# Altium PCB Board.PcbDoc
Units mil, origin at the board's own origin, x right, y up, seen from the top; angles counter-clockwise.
Board outline 3917.32 x 3145.67 mil, 2 copper layers (Top Layer, Bottom Layer); 52 components, 39 nets, 493 pads, 14 vias.
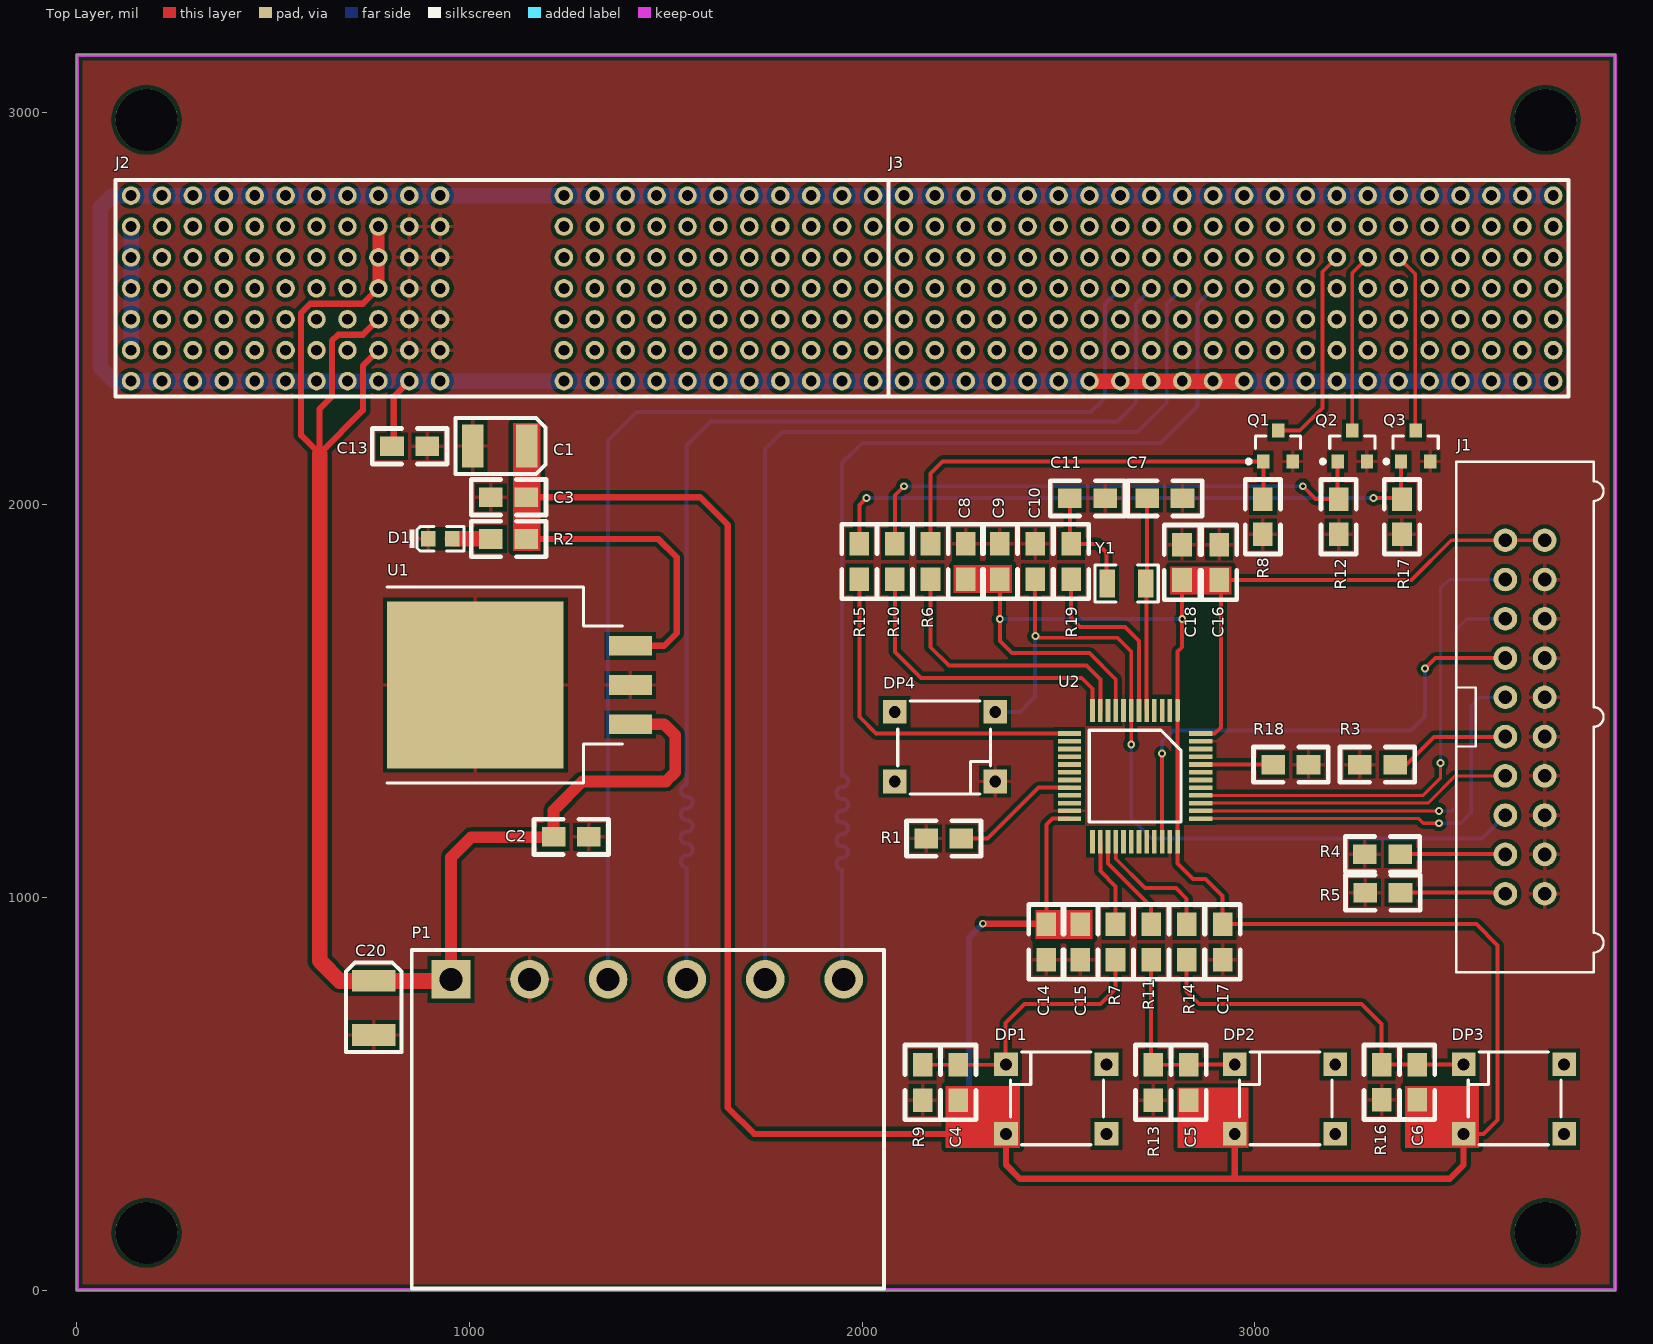
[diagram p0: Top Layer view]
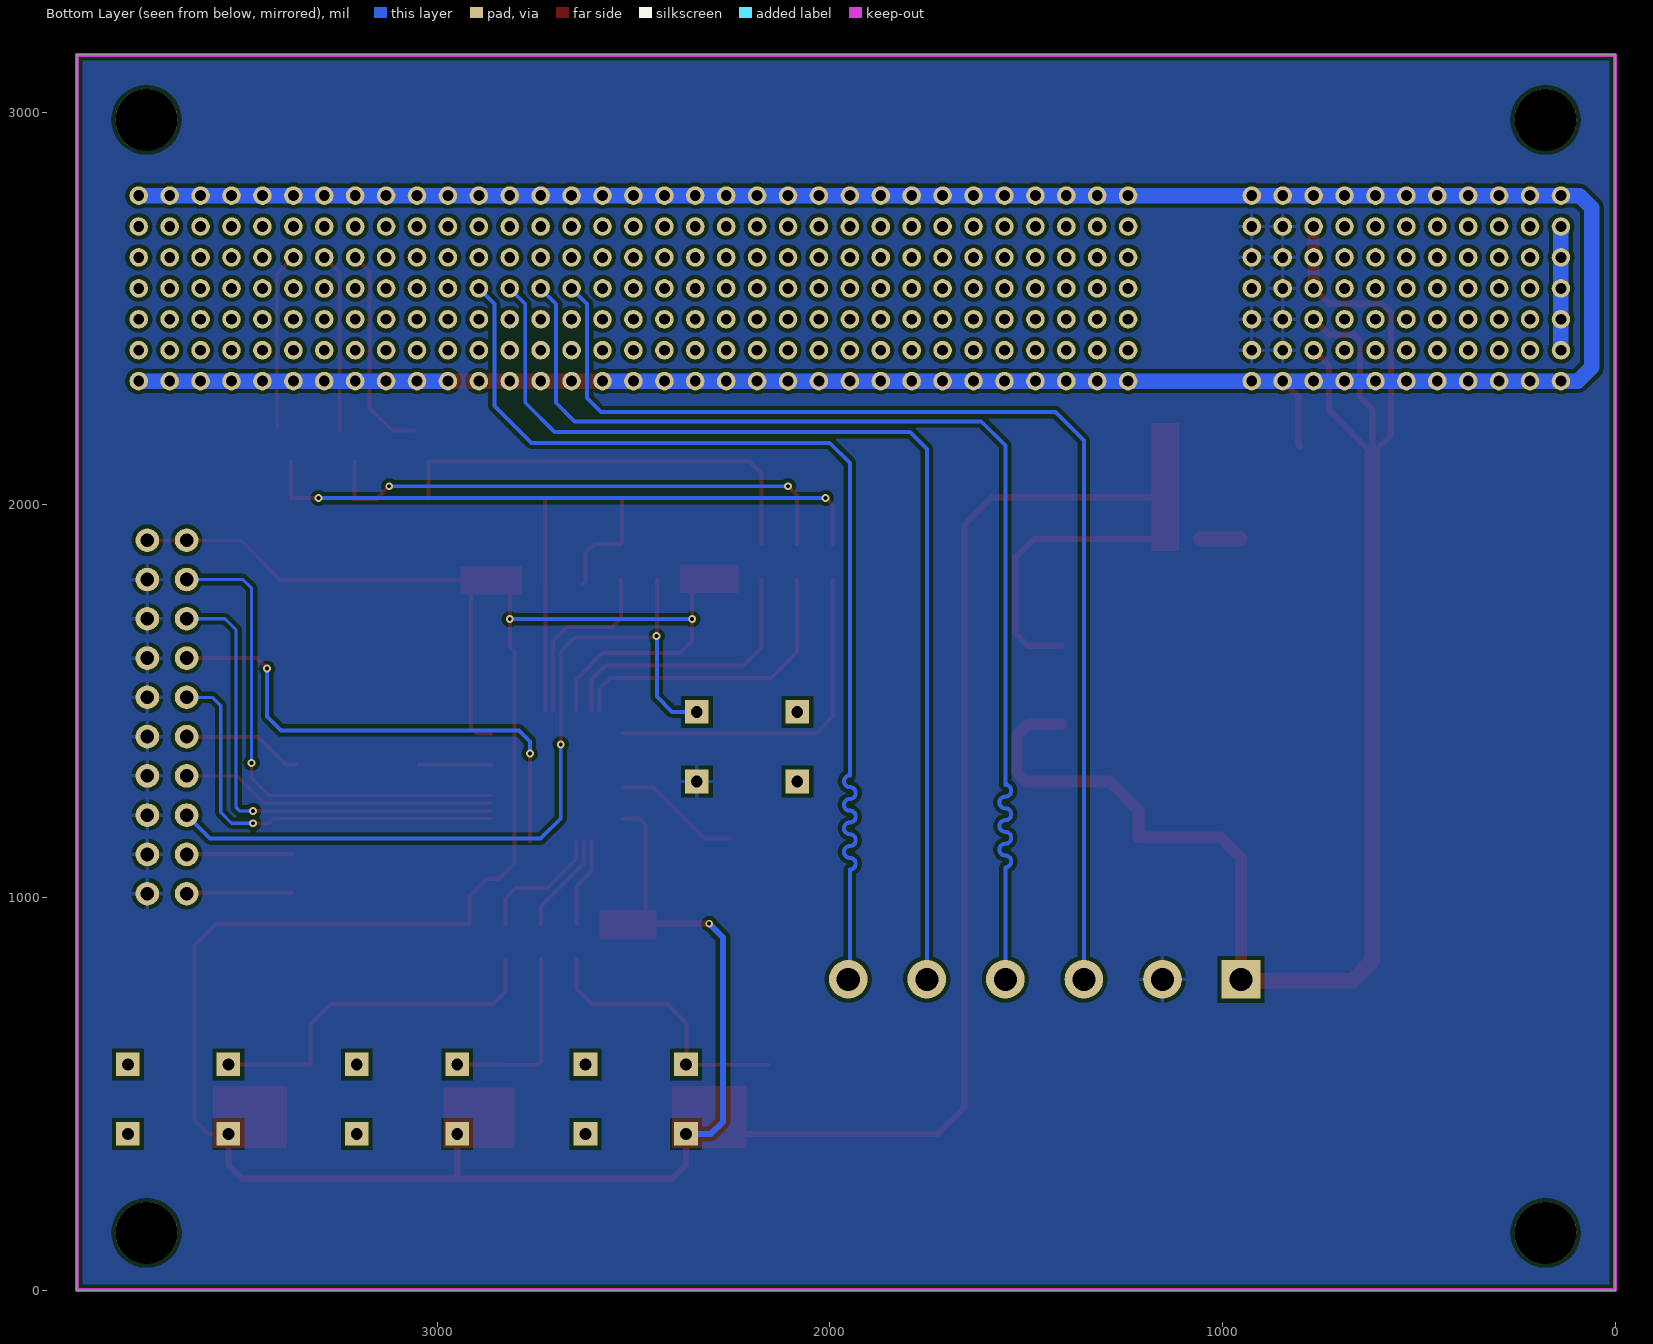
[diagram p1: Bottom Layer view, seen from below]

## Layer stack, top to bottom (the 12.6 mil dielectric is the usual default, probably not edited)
Top Layer: signal copper 1.4
Dielectric: dielectric 12.6, FR-4, Dk 4.8
Bottom Layer: signal copper 1.4

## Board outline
0,3145.67 0,0 3917.32,0 3917.32,3145.67 0,3145.67

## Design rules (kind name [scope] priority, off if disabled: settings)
Clearance Clearance_2 [(InNamedPolygon('Top Layer-No Net 1'))] p1: gap=10
Clearance Clearance_1 [(InComponent('U2'))] p2: gap=7.87
Clearance [All] p3: gap=7.8
ComponentClearance [All] p1: gap=0 collisioncheckmode=3 verticalgap=0 showdistances=FALSE
DiffPairsRouting [All] p1: maxlimit=10 minlimit=10 mostfreqgap=10 maxuncoupledlength=500
PolygonConnect [All] p1: connectstyle=Relief reliefconductorwidth=10 reliefentries=4 polygonreliefangle="90 Angle"
RoutingVias [All] p1: holewidth=10 width=20 viastyle="Through Hole" minholewidth=10 minwidth=20 maxholewidth=28 maxwidth=50
SilkToSilkClearance [All] p1: silktosilkclearance=0
SilkscreenOverComponentPads [All] p1: minsilkscreentomaskgap=0
SolderMaskExpansion [All] p1: expansion=4
Width [All] p1: maxlimit=40 minlimit=5 preferedwidth=10 minimp=50.000000 maximp=50.000000 favimp=50.000000
24 further rules are at their usual default settings.

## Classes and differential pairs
differential pair CAN2: +CAN2_P -CAN2_N
differential pair CAN1: +CAN1_P -CAN1_N

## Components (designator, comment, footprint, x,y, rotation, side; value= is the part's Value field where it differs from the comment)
C1 "106" TC_B_3528 1145.67,2149.61 r180 top
C2 "104" 0805 1303.15,1153.54 r180 top
C3 "104" 0805 1055.12,2019.69 r0 top
C4 "104" 0805 2244.09,484.64 r90 top
C5 "104" 0805 2830.71,484.64 r90 top
C6 "104" 0805 3412.83,484.97 r90 top
C7 "20p" 0805 2814.96,2015.75 r180 top
C8 "104" 0805 2264.33,1899.59 r270 top
C9 "105" 0805 2350.94,1899.59 r270 top
C10 "104" 0805 2440.94,1899.59 r270 top
C11 "20p" 0805 2618.11,2015.75 r180 top
C13 "103" 0805 803.15,2149.61 r0 top
C14 "104" 0805 2468.5,842.52 r90 top
C15 "104" 0805 2555.12,842.52 r90 top
C16 "104" 0805 2909.45,1897.64 r270 top
C17 "106" 0805 2917.32,842.52 r90 top
C18 "104" 0805 2814.96,1897.64 r270 top
C20 "106" TC_B_3528 755.91,787.4 r270 top
D1 "LED" 0603_LED_S1 925.2,1913.39 r0 top
DP1 "SW-PB" PB_6X6 2366.14,574.8 r0 top
DP2 "SW-PB" PB_6X6 2948.82,574.8 r0 top
DP3 "SW-PB" PB_6X6 3531.5,574.8 r0 top
DP4 "SW-PB" PB_6X6 2338.58,1295.28 r180 top
J1 "JTAG-L" JTAG-20P 3692.91,1464.57 r0 top
J2 "CPCI_H2A1541A" CPCI_H2A1541A 137.8,2787.4 r0 top
J3 "CPCI_H2B21541A" CPCI_H2B21541A 2106.3,2787.4 r0 top
P1 "CON-6P" CON-5.08-6P 952.76,791.34 r0 top
Q1 "MMBT4401LT1G" ONSC-SOT-23-3-318-08_V 3059.06,2149.61 r90 top
Q2 "MMBT4401LT1G" ONSC-SOT-23-3-318-08_V 3248.03,2149.61 r90 top
Q3 "MMBT4401LT1G" ONSC-SOT-23-3-318-08_V 3409.45,2149.61 r90 top
R1 "10K" 0805 2251.97,1149.61 r180 top
R2 "1K" 0805 1055.12,1913.39 r0 top
R3 "10K" 0805 3267.72,1338.58 r0 top
R4 "10K" 0805 3369.36,1109.69 r180 top
R5 "10K" 0805 3370.08,1011.81 r180 top
R6 "1K" 0805 2173.23,1811.02 r90 top
R7 "1K" 0805 2645.67,931.08 r270 top
R8 "10K" 0805 3019.68,1925.2 r90 top
R9 "4K7" 0805 2153.54,484.64 r90 top
R10 "1K" 0805 2082.68,1811.02 r90 top
R11 "1K" 0805 2736.22,931.08 r270 top
R12 "10K" 0805 3212.6,1925.2 r90 top
R13 "4K7" 0805 2740.16,484.64 r90 top
R14 "1K" 0805 2826.77,931.08 r270 top
R15 "1K" 0805 1992.13,1811.02 r90 top
R16 "4K7" 0805 3322.28,484.97 r90 top
R17 "10K" 0805 3374.02,1925.2 r90 top
R18 "10K" 0805 3047.24,1338.58 r0 top
R19 "0R" 0805 2531.5,1811.02 r90 top
U1 "MIC29150" TO263 1409.45,1440.94 r90 top
U2 "STM32F103C8T6" LQFP48 2803.15,1476.38 r270 top
Y1 "8MHz" "SMD-3215_2P FC - 135" 2673.23,1799.21 r0 top

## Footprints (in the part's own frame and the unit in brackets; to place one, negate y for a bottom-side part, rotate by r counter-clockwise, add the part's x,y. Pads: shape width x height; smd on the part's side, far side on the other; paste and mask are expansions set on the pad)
0603_LED_S1 [mm]
  rect 0.93x0.98 smd: A(0.77,0) K(-0.77,0)
  silkscreen extent -1.98,-0.79 1.54,0.79, body extent -0.8,-0.4 0.8,0.4, height 0.6
0805 [mil]
  rect 60x50 smd: 1(-0.72,-0.55) 2(89.28,-0.55)
  silkscreen extent -51,-46 139,44
CON-5.08-6P [mm]
  rect 2.5x2.5 hole 1.5: 1(0,0)
  round 2.5 hole 1.5 paste+0: 2(5.08,0) 3(10.16,0) 4(15.24,0) 5(20.32,0) 6(25.4,0)
  silkscreen extent -2.54,-20 28,1.91
CPCI_H2A1541A [mm]
  round 1.2 hole 0.7: A1(0,0) A2(2,0) A3(4,0) A4(6,0) A5(8,0) A6(10,0) A7(12,0) A8(14,0) A9(16,0) A10(18,0) A11(20,0) A15(28,0) A16(30,0) A17(32,0) A18(34,0) A19(36,0) A20(38,0) A21(40,0) A22(42,0) A23(44,0) A24(46,0) A25(48,0) B1(0,-2) B2(2,-2) B3(4,-2) B4(6,-2) B5(8,-2) B6(10,-2) B7(12,-2) B8(14,-2) B9(16,-2) B10(18,-2) B11(20,-2) B15(28,-2) B16(30,-2) B17(32,-2) B18(34,-2) B19(36,-2) B20(38,-2) B21(40,-2) B22(42,-2) B23(44,-2) B24(46,-2) B25(48,-2) C1(0,-4) C2(2,-4) C3(4,-4) C4(6,-4) C5(8,-4) C6(10,-4) C7(12,-4) C8(14,-4) C9(16,-4) C10(18,-4) C11(20,-4) C15(28,-4) C16(30,-4) C17(32,-4) C18(34,-4) C19(36,-4) C20(38,-4) C21(40,-4) C22(42,-4) C23(44,-4) C24(46,-4) C25(48,-4) D1(0,-6) D2(2,-6) D3(4,-6) D4(6,-6) D5(8,-6) D6(10,-6) D7(12,-6) D8(14,-6) D9(16,-6) D10(18,-6) D11(20,-6) D15(28,-6) D16(30,-6) D17(32,-6) D18(34,-6) D19(36,-6) D20(38,-6) D21(40,-6) D22(42,-6) D23(44,-6) D24(46,-6) D25(48,-6) E1(0,-8) E2(2,-8) E3(4,-8) E4(6,-8) E5(8,-8) E6(10,-8) E7(12,-8) E8(14,-8) E9(16,-8) E10(18,-8) E11(20,-8) E15(28,-8) E16(30,-8) E17(32,-8) E18(34,-8) E19(36,-8) E20(38,-8) E21(40,-8) E22(42,-8) E23(44,-8) E24(46,-8) E25(48,-8) F1(0,-10) F2(2,-10) F3(4,-10) F4(6,-10) F5(8,-10) F6(10,-10) F7(12,-10) F8(14,-10) F9(16,-10) F10(18,-10) F11(20,-10) F15(28,-10) F16(30,-10) F17(32,-10) F18(34,-10) F19(36,-10) F20(38,-10) F21(40,-10) F22(42,-10) F23(44,-10) F24(46,-10) F25(48,-10) G1(0,-12) G2(2,-12) G3(4,-12) G4(6,-12) G5(8,-12) G6(10,-12) G7(12,-12) G8(14,-12) G9(16,-12) G10(18,-12) G11(20,-12) G15(28,-12) G16(30,-12) G17(32,-12) G18(34,-12) G19(36,-12) G20(38,-12) G21(40,-12) G22(42,-12) G23(44,-12) G24(46,-12) G25(48,-12)
  silkscreen extent -1,-13 49,1
CPCI_H2B21541A [mm]
  round 1.2 hole 0.7: A1(0,0) A2(2,0) A3(4,0) A4(6,0) A5(8,0) A6(10,0) A7(12,0) A8(14,0) A9(16,0) A10(18,0) A11(20,0) A12(22,0) A13(24,0) A14(26,0) A15(28,0) A16(30,0) A17(32,0) A18(34,0) A19(36,0) A20(38,0) A21(40,0) A22(42,0) B1(0,-2) B2(2,-2) B3(4,-2) B4(6,-2) B5(8,-2) B6(10,-2) B7(12,-2) B8(14,-2) B9(16,-2) B10(18,-2) B11(20,-2) B12(22,-2) B13(24,-2) B14(26,-2) B15(28,-2) B16(30,-2) B17(32,-2) B18(34,-2) B19(36,-2) B20(38,-2) B21(40,-2) B22(42,-2) C1(0,-4) C2(2,-4) C3(4,-4) C4(6,-4) C5(8,-4) C6(10,-4) C7(12,-4) C8(14,-4) C9(16,-4) C10(18,-4) C11(20,-4) C12(22,-4) C13(24,-4) C14(26,-4) C15(28,-4) C16(30,-4) C17(32,-4) C18(34,-4) C19(36,-4) C20(38,-4) C21(40,-4) C22(42,-4) D1(0,-6) D2(2,-6) D3(4,-6) D4(6,-6) D5(8,-6) D6(10,-6) D7(12,-6) D8(14,-6) D9(16,-6) D10(18,-6) D11(20,-6) D12(22,-6) D13(24,-6) D14(26,-6) D15(28,-6) D16(30,-6) D17(32,-6) D18(34,-6) D19(36,-6) D20(38,-6) D21(40,-6) D22(42,-6) E1(0,-8) E2(2,-8) E3(4,-8) E4(6,-8) E5(8,-8) E6(10,-8) E7(12,-8) E8(14,-8) E9(16,-8) E10(18,-8) E11(20,-8) E12(22,-8) E13(24,-8) E14(26,-8) E15(28,-8) E16(30,-8) E17(32,-8) E18(34,-8) E19(36,-8) E20(38,-8) E21(40,-8) E22(42,-8) F1(0,-10) F2(2,-10) F3(4,-10) F4(6,-10) F5(8,-10) F6(10,-10) F7(12,-10) F8(14,-10) F9(16,-10) F10(18,-10) F11(20,-10) F12(22,-10) F13(24,-10) F14(26,-10) F15(28,-10) F16(30,-10) F17(32,-10) F18(34,-10) F19(36,-10) F20(38,-10) F21(40,-10) F22(42,-10) G1(0,-12) G2(2,-12) G3(4,-12) G4(6,-12) G5(8,-12) G6(10,-12) G7(12,-12) G8(14,-12) G9(16,-12) G10(18,-12) G11(20,-12) G12(22,-12) G13(24,-12) G14(26,-12) G15(28,-12) G16(30,-12) G17(32,-12) G18(34,-12) G19(36,-12) G20(38,-12) G21(40,-12) G22(42,-12)
  silkscreen extent -1,-13 43,1
JTAG-20P [mil]
  round 60 hole 35: 1(-55,445) 2(45,445) 3(-55,345) 4(45,345) 5(-55,245) 6(45,245) 7(-55,145) 8(45,145) 9(-55,45) 10(45,45) 11(-55,-55) 12(45,-55) 13(-55,-155) 14(45,-155) 15(-55,-255) 16(45,-255) 17(-55,-355) 18(45,-355) 19(-55,-455) 20(45,-455)
  silkscreen extent -180,-655 195,645
LQFP48 [mm]
  oval 1.5x0.3 smd: 1(0,0)
  rect 1.5x0.3 smd: 2(0,-0.5) 3(0,-1) 4(0,-1.5) 5(0,-2) 6(0,-2.5) 7(0,-3) 8(0,-3.5) 9(0,-4) 10(0,-4.5) 11(0,-5) 12(0,-5.5) 25(8.5,-5.5) 26(8.5,-5) 27(8.5,-4.5) 28(8.5,-4) 29(8.5,-3.5) 30(8.5,-3) 31(8.5,-2.5) 32(8.5,-2) 33(8.5,-1.5) 34(8.5,-1) 35(8.5,-0.5) 36(8.5,0)
  rect 0.3x1.5 smd: 13(1.5,-7) 14(2,-7) 15(2.5,-7) 16(3,-7) 17(3.5,-7) 18(4,-7) 19(4.5,-7) 20(5,-7) 21(5.5,-7) 22(6,-7) 23(6.5,-7) 24(7,-7) 37(7,1.5) 38(6.5,1.5) 39(6,1.5) 40(5.5,1.5) 41(5,1.5) 42(4.5,1.5) 43(4,1.5) 44(3.5,1.5) 45(3,1.5) 46(2.5,1.5) 47(2,1.5) 48(1.5,1.5)
  silkscreen extent 1.28,-5.71 7.21,0.22
ONSC-SOT-23-3-318-08_V [mm] "SOT23, 3-Leads, Body 2.92x1.3mm, Pitch 0.95mm"
  rect 0.9x0.8 smd: 1(-1,0.95) 2(-1,-0.95) 3(1,0)
  silkscreen extent -1.12,-1.46 0.65,2.02, body extent -0.65,-1.46 0.65,1.46, height 1.11
PB_6X6 [mil]
  rect 60x60 hole 30: 1(0,0) 2(0,-177.17) 3(255.91,0) 4(255.91,-177.17)
  silkscreen extent 12,-205 248,31
"SMD-3215_2P FC - 135" [mm]
  rect 1x1.8 smd: 1(-1.25,0) 2(1.25,0)
  silkscreen extent -2.05,-1.2 2.05,1.2
TC_B_3528 [mm]
  rect 1.4x2.8 smd: 1(0,0) 2(3.5,0)
  silkscreen extent -1.2,-1.8 4.6,1.8
TO263 [mil]
  rect 50x110 smd: 1(0,0) 2(100,0) 3(200,0)
  rect 425x450 smd: 4(100,394.69)
  silkscreen extent -150,20 350,620

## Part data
C1 C20: library part "CAP POL1", "Capacitor"
C2 C3 C4 C5 C6 C7 C8 C9 C10 C11 C13 C14 C15 C16 C17 C18: library part CAP
DP1 DP2 DP3 DP4: "Key"
J1: "Connector"
Q1 Q2 Q3: "Switching Transistor, NPN Silicon, 3-Pin SOT-23, Pb-Free, Tape and Reel"
R1 R2 R3 R4 R5 R6 R7 R8 R9 R10 R11 R12 R13 R14 R15 R16 R17 R18 R19: library part RES1
U2: library part STM32F103C6T6, "ST ARM-based 32-bit MCU with 32 KB Flash, USB, CAN, 7 timers, 2 ADCs, 9 com. interfaces"
Y1: library part "XTAL-3215_2P 32.768KHz", "ÌùÆ¬¾"

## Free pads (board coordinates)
  round 157.48 hole 157.48: 0(177.17,145.67) 1(3740.16,145.67) 2(3740.16,2980.31) 3(177.17,2980.31)

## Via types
v1: diameter 20, hole 10, Top Layer to Bottom Layer, tented both sides, 14 vias

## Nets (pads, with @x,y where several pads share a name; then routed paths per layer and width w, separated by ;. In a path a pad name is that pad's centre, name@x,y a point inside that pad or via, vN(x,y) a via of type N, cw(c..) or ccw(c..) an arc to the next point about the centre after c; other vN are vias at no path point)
3V3: C1.1 C3.2 C4.1 C5.1 C6.1 C8.2 C9.2 C14.2 C15.2 C16.2 C17.2 C18.2 DP1.2 DP2.2 DP3.2 J1.1 J1.2 R2.2 U1.3 U2.1 U2.9 U2.24 U2.36 U2.48 | length 10644.2
  Top Layer w10: C3.2 C3.2@1160.7,2035.43 ; C9.2 v1(2350.39,1708.66) 2350.39,1653.54 2381.89,1622.05 2578.74,1622.05 2645.67,1555.12 U2.9 ; C14.2 2469.05,1185.59 2484.25,1200.79 U2.24 ; C18.2 2814.41,1637.24 2803.15,1625.98 U2.1 U2.36 2803.15,1086.61 2842.52,1047.24 2874.02,1047.24 2917.87,1003.39 C17.2 3564.26,931.8 3618.11,877.95 3618.11,433.07 3582.68,397.64 DP3.2 ; U2.48 2897.64,1417.32 2913.39,1433.07 2913.39,1803.87 C16.2 3398.91,1808.36 3500.12,1909.57 J1.1 J1.2
  Top Layer w15.75: R2.2 1480.87,1912.83 1527.56,1866.14 1527.56,1673.23 1495.28,1640.94 U1.3 ; C3.2 1587.17,2019.13 1657.48,1948.82 1657.48,464.57 1724.41,397.64 DP1.2 2366.14,318.9 2401.57,283.46 3496.06,283.46 3531.5,318.9 DP3.2 ; v1(2307.09,933.07) 2467.79,933.07 C14.2 ; 2948.82,283.46 DP2.2
  Bottom Layer w10: v1(2350.39,1708.66) v1(2814.96,1708.66)
  Bottom Layer w15.75: v1(2307.09,933.07) 2271.65,897.64 2271.65,429.13 2303.15,397.64 DP1.2
28V: J2.B1 J2.C1 J2.D1 J2.E1 J2.F1 | length 315
  Bottom Layer w39.37: J2.F1 J2.D1 J2.C1 J2.B1
CAN1_N: J3.D9 P1.4 | length 2976.3
  Bottom Layer w10: P1.4 1552.76,1076.69 cw(c1552.76,1091.69) 1552.76,1106.69 ccw(c1552.76,1121.69) 1552.76,1136.69 cw(c1552.76,1151.69) 1552.76,1166.69 ccw(c1552.76,1181.69) 1552.76,1196.69 ; 1552.76,1196.85 cw(c1552.76,1211.85) 1552.76,1226.85 ccw(c1552.76,1241.85) 1552.76,1256.85 cw(c1552.76,1271.85) 1552.76,1286.85 1552.76,2151.18 1614.17,2212.6 2649.61,2212.6 2696.85,2259.84 2696.85,2511.81 J3.D9
CAN1_P: J3.D8 P1.3 | length 2978.3
  Bottom Layer w10: P1.3 1352.76,2163.78 1425.2,2236.22 2582.68,2236.22 2618.11,2271.65 2618.11,2511.81 J3.D8
CAN2_N: J3.D11 P1.6 | length 2733.3
  Bottom Layer w10: P1.6@1948.82,791.34 1948.82,1070.87 cw(c1948.82,1085.87) 1948.82,1100.87 ccw(c1948.82,1115.87) 1948.82,1130.87 cw(c1948.82,1145.87) 1948.82,1160.87 ccw(c1948.82,1175.87) 1948.82,1190.87 cw(c1948.82,1205.87) 1948.82,1220.87 ccw(c1948.82,1235.87) 1948.82,1250.87 cw(c1948.82,1265.87) 1948.82,1280.87 ccw(c1948.82,1295.87) 1948.82,1310.87 1948.82,2106.3 2000,2157.48 2759.84,2157.48 2854.33,2251.97 2854.33,2511.81 J3.D11
CAN2_P: J3.D10 P1.5 | length 2738.1
  Bottom Layer w10: P1.5@1752.76,783.46 1752.76,2142.52 1795.28,2185.04 2700.79,2185.04 2775.59,2259.84 2775.59,2511.81 J3.D10
GND: C1.2 C2.1 C3.1 C7.1 C8.1 C9.1 C10.1 C11.1 C13.2 C14.1 C15.1 C16.1 C17.1 C18.1 C20.2 D1.K DP4.1 J1.4 J1.6 J1.8 J1.10 J1.12 J1.14 J1.16 J1.18 J1.20 J2.B10 J2.B11 J2.C10 J2.C11 J2.D10 J2.E10 J2.E11 J2.F10 J2.F11 P1.2 Q1.2 Q2.2 Q3.2 R1.2 R3.1 R4.2 R5.2 R8.1 R9.1 R12.1 R13.1 R16.1 R17.1 R18.2 U1.2 U1.4 U2.8 U2.23 U2.35 U2.47
KEY_OFF: R11.1 U2.27 | length 255.4
  Top Layer w10: U2.27 2625.98,1086.61 2735.67,976.93 R11.1
KEY_ON: R7.1 U2.26 | length 226
  Top Layer w10: U2.26 2606.3,1066.93 2645.12,1028.11 R7.1
KEY_RESET: R14.1 U2.28 | length 330.8
  Top Layer w10: U2.28 2645.67,1098.42 2720.47,1023.62 2799.21,1023.62 2826.22,996.61 R14.1
NetC4_2: C4.2 DP1.1 R7.2 R9.2 | length 708
  Top Layer w10: R9.2 C4.2 2365.26,573.92 2365.26,680.22 2413.39,728.35 2606.3,728.35 2645.12,767.17 R7.2
NetC5_2: C5.2 DP2.1 R11.2 R13.2 | length 477.2
  Top Layer w10: R11.2 2735.67,578.96 R13.2 C5.2 ; C5.2@2832.14,574.8 DP2.1
NetC6_2: C6.2 DP3.1 R14.2 R16.2 | length 924.3
  Top Layer w10: R14.2 2826.22,760.39 2858.27,728.35 3271.65,728.35 3322.83,677.17 R16.2 C6.2 3530.94,574.25 DP3.1
NetC11_2: C11.2 R19.2 Y1.1 | length 293.2
  Top Layer w10: R19.2@2528.83,1903.52 C11.2 ; R19.2 2599.69,1900.31 2622.05,1877.95 2622.05,1805.12 Y1.1@2627.95,1799.21
NetD1_A: D1.A R2.1 | length 98.3
  Top Layer w39.37: D1.A R2.1@1053.85,1913.39
NetJ1_11: J1.11 R3.2 | length 309.4
  Top Layer w10: R3.2@3357,1338.58 3385.83,1338.58 3456.14,1408.9 J1.11@3637.25,1408.9
NetJ1_17: J1.17 R4.1 | length 267.2
  Top Layer w10: R4.1 J1.17@3637.24,1110.24
NetJ1_19: J1.19 R5.1 | length 264.3
  Top Layer w10: R5.1 J1.19@3635.12,1012.36
NetQ1_1: Q1.1 R6.2 R8.2 | length 1134
  Top Layer w10: R6.2 2173.78,2079.29 2204.72,2110.24 Q1.1 R8.2@3021.65,2015.9
NetQ2_1: Q2.1 R10.2 R12.2 | length 1370.2
  Top Layer w10: R10.2 2083.23,2024.17 v1(2106.3,2047.24) ; v1(3122.05,2047.24) 3154.81,2014.48 R12.2 ; R12.2@3210.63,2017 Q2.1
  Bottom Layer w10: v1(2106.3,2047.24) v1(3122.05,2047.24)
NetQ3_1: Q3.1 R15.2 R17.2 | length 1578.8
  Top Layer w10: R15.2 1992.68,1999.11 v1(2010.56,2017) ; v1(3301.9,2017) 3372.05,2017 Q3.1
  Bottom Layer w10: v1(2010.56,2017) v1(3301.9,2017)
NetR1_1: R1.1 U2.20 | length 328.5
  Top Layer w10: R1.1 2319.45,1150.16 2448.82,1279.53 U2.20
NetR18_1: R18.1 U2.44 | length 183.8
  Top Layer w10: U2.44 R18.1@3045.97,1338.58
NRST: C10.2 DP4.2 J1.15 U2.7 | length 2101.7
  Top Layer w10: C10.2 2440.39,1665.91 v1(2440.94,1665.35) 2444.88,1661.42 2649.61,1661.42 2685.04,1625.98 U2.7 v1(2685.04,1389.76)
  Bottom Layer w10: DP4.2 2401.57,1472.44 2440.39,1511.26 v1@2440.39,1665.35 ; v1(2685.04,1389.76) 2685.04,1200.79 2736.22,1149.61 3577.95,1149.61 J1.15
NTRST: J1.3 U2.40 | length 1287.1
  Top Layer w8: U2.40 3429.13,1259.84 3472.44,1303.15 v1(3472.44,1342.52)
  Bottom Layer w8: v1(3472.44,1342.52) 3472.44,1787.4 3494.61,1809.57 J1.3
OC1_ON: J3.C15 Q1.3 | length 535.2
  Top Layer w10: Q1.3 3114.17,2188.98 3172.17,2246.97 3172.17,2593.43 J3.C15
OC2_OFF: J3.C16 Q2.3 | length 457.3
  Top Layer w10: Q2.3 3248.03,2590.55 J3.C16
OC3_RESET: J3.C17 Q3.3 | length 449.5
  Top Layer w10: J3.C17 3408.39,2587.68 Q3.3@3408.39,2197.91
OSC_IN: C7.2 U2.5 Y1.2 | length 538.8
  Top Layer w10: Y1.2 2723.5,1798.15 U2.5@2723.5,1477.28 ; Y1.2@2725.68,1799.91 C7.2
OSC_OUT: R19.1 U2.6 | length 472.3
  Top Layer w10: R19.1 2532.05,1712.05 2555.12,1688.98 2669.29,1688.98 2704.72,1653.54 U2.6
PGND: C13.1 J2.A1 J2.A2 J2.A3 J2.A4 J2.A5 J2.A6 J2.A7 J2.A8 J2.A9 J2.A10 J2.A11 J2.A15 J2.A16 J2.A17 J2.A18 J2.A19 J2.A20 J2.A21 J2.A22 J2.A23 J2.A24 J2.A25 J2.G1 J2.G2 J2.G3 J2.G4 J2.G5 J2.G6 J2.G7 J2.G8 J2.G9 J2.G10 J2.G11 J2.G15 J2.G16 J2.G17 J2.G18 J2.G19 J2.G20 J2.G21 J2.G22 J2.G23 J2.G24 J2.G25 J3.A1 J3.A2 J3.A3 J3.A4 J3.A5 J3.A6 J3.A7 J3.A8 J3.A9 J3.A10 J3.A11 J3.A12 J3.A13 J3.A14 J3.A15 J3.A16 J3.A17 J3.A18 J3.A19 J3.A20 J3.A21 J3.A22 J3.G1 J3.G2 J3.G3 J3.G4 J3.G5 J3.G6 J3.G7 J3.G8 J3.G9 J3.G10 J3.G11 J3.G12 J3.G13 J3.G14 J3.G15 J3.G16 J3.G17 J3.G18 J3.G19 J3.G20 J3.G21 J3.G22 | length 8022.9
  Top Layer w15.75: C13.1 807.09,2153.71 807.09,2275.59 J2.G10 J2.G10@846.46,2311.02
  Top Layer w39.37: J3.G7 J3.G8 J3.G9 J3.G10 J3.G11 J3.G12
  Bottom Layer w39.37: J3.G7 J3.G6 J3.G5 J3.G4 J3.G3 J3.G2 J3.G1 J2.G25 J2.G24 J2.G23 J2.G22 J2.G21 J2.G20 J2.G19 J2.G18 J2.G17 J2.G16 J2.G15 J2.G11 J2.G10 J2.G9 J2.G7 J2.G6 J2.G5 J2.G4 J2.G3 J2.G2 J2.G1 94.49,2314.96 59.06,2350.39 59.06,2755.91 90.55,2787.4 J2.A1 J2.A2 J2.A3 J2.A4 J2.A5 J2.A6 J2.A7 J2.A8 J2.A9 J2.A10 J2.A11 J2.A15 J2.A16 J2.A17 J2.A18 J2.A19 J2.A20 J2.A21 J2.A22 J2.A23 J2.A24 J2.A25 J3.A1 J3.A2 J3.A3 J3.A4 J3.A5 J3.A6 J3.A7 J3.A8 J3.A9 J3.A10 J3.A11 J3.A12 J3.A13 J3.A14 J3.A15 J3.A16 J3.A17 J3.A18 J3.A19 J3.A20 J3.A21 J3.A22 ; J3.G12 J3.G13 J3.G14 J3.G15 J3.G16 J3.G17 J3.G18 J3.G19 J3.G20 J3.G21 J3.G22
TCK: J1.9 U2.37 | length 1072.5
  Top Layer w8: U2.37 3417.32,1200.79 3429.13,1188.98 v1(3468.5,1188.98)
  Bottom Layer w8: v1(3468.5,1188.98) 3523.62,1188.98 3551.18,1216.54 3551.18,1488.19 3572.56,1509.57 J1.9
TDI: J1.5 U2.38 | length 1243.5
  Top Layer w8: U2.38 v1(3468.5,1220.47)
  Bottom Layer w8: v1(3468.5,1220.47) 3503.94,1220.47 3511.81,1228.35 3511.81,1681.1 3540.28,1709.57 J1.5
TDO: J1.13 U2.39 | length 804.5
  Top Layer w8: U2.39 3440.95,1240.16 3510.35,1309.57 J1.13
TIM2_2: R6.1 U2.11 | length 718.3
  Top Layer w10: R6.1 2173.78,1637.24 2220.47,1590.55 2570.87,1590.55 2606.3,1555.12 U2.11
TIM2_3: R10.1 U2.12 | length 782.3
  Top Layer w10: R10.1 2083.23,1625.43 2149.61,1559.06 2559.06,1559.06 2586.61,1531.5 U2.12
TIM2_4: R15.1 U2.13 | length 902.8
  Top Layer w10: R15.1 1992.68,1460.08 2035.43,1417.32 U2.13
TMS: J1.7 U2.34 | length 1289.3
  Top Layer w10: U2.34 v1(2763.78,1366.14) ; v1(3433.07,1582.68) 3459.96,1609.57 J1.7
  Bottom Layer w10: v1(2763.78,1366.14) 2763.78,1397.64 2791.34,1425.2 3397.64,1425.2 3433.07,1460.63 v1(3433.07,1582.68)
VIN_12V: C2.2 C20.1 J2.B9 J2.C9 J2.D9 J2.E9 J2.F9 P1.1 U1.1 | length 4392.6
  Top Layer w15.74: 618.11,2129.92 728.35,2240.16 728.35,2354.33 J2.F9
  Top Layer w15.75: J2.E9 728.42,2433.14 665.43,2433.14 649.53,2417.25 649.53,2275.66 618.11,2244.24 618.11,2129.92 570.87,2177.17 570.87,2488.64 594.11,2511.89 728.27,2511.89 767.57,2551.18 J2.D9
  Top Layer w30: J2.D9 J2.C9 J2.B9 ; P1.1 952.76,1102.36 1003.94,1153.54 C2.2@1206.54,1153.54 ; C2.2 1213.87,1221.74 1287.4,1295.28 1500,1295.28 1523.62,1318.9 1523.62,1413.39 1496.06,1440.94 U1.1
  Top Layer w40: 618.11,2129.92 618.11,838.58 669.29,787.4 C20.1 P1.1@948.82,787.4
pads on no net: DP1.3 DP1.4 DP2.3 DP2.4 DP3.3 DP3.4 DP4.3 DP4.4 J2.B2 J2.B3 J2.B4 J2.B5 J2.B6 J2.B7 J2.B8 J2.B15 J2.B16 J2.B17 J2.B18 J2.B19 J2.B20 J2.B21 J2.B22 J2.B23 J2.B24 J2.B25 J2.C2 J2.C3 J2.C4 J2.C5 J2.C6 J2.C7 J2.C8 J2.C15 J2.C16 J2.C17 J2.C18 J2.C19 J2.C20 J2.C21 J2.C22 J2.C23 J2.C24 J2.C25 J2.D2 J2.D3 J2.D4 J2.D5 J2.D6 J2.D7 J2.D8 J2.D11 J2.D15 J2.D16 J2.D17 J2.D18 J2.D19 J2.D20 J2.D21 J2.D22 J2.D23 J2.D24 J2.D25 J2.E2 J2.E3 J2.E4 J2.E5 J2.E6 J2.E7 J2.E8 J2.E15 J2.E16 J2.E17 J2.E18 J2.E19 J2.E20 J2.E21 J2.E22 J2.E23 J2.E24 J2.E25 J2.F2 J2.F3 J2.F4 J2.F5 J2.F6 J2.F7 J2.F8 J2.F15 J2.F16 J2.F17 J2.F18 J2.F19 J2.F20 J2.F21 J2.F22 J2.F23 J2.F24 J2.F25 J3.B1 J3.B2 J3.B3 J3.B4 J3.B5 J3.B6 J3.B7 J3.B8 J3.B9 J3.B10 J3.B11 J3.B12 J3.B13 J3.B14 J3.B15 J3.B16 J3.B17 J3.B18 J3.B19 J3.B20 J3.B21 J3.B22 J3.C1 J3.C2 J3.C3 J3.C4 J3.C5 J3.C6 J3.C7 J3.C8 J3.C9 J3.C10 J3.C11 J3.C12 J3.C13 J3.C14 J3.C18 J3.C19 J3.C20 J3.C21 J3.C22 J3.D1 J3.D2 J3.D3 J3.D4 J3.D5 J3.D6 J3.D7 J3.D12 J3.D13 J3.D14 J3.D15 J3.D16 J3.D17 J3.D18 J3.D19 J3.D20 J3.D21 J3.D22 J3.E1 J3.E2 J3.E3 J3.E4 J3.E5 J3.E6 J3.E7 J3.E8 J3.E9 J3.E10 J3.E11 J3.E12 J3.E13 J3.E14 J3.E15 J3.E16 J3.E17 J3.E18 J3.E19 J3.E20 J3.E21 J3.E22 J3.F1 J3.F2 J3.F3 J3.F4 J3.F5 J3.F6 J3.F7 J3.F8 J3.F9 J3.F10 J3.F11 J3.F12 J3.F13 J3.F14 J3.F15 J3.F16 J3.F17 J3.F18 J3.F19 J3.F20 J3.F21 J3.F22 U2.2 U2.3 U2.4 U2.10 U2.14 U2.15 U2.16 U2.17 U2.18 U2.19 U2.21 U2.22 U2.25 U2.29 U2.30 U2.31 U2.32 U2.33 U2.41 U2.42 U2.43 U2.45 U2.46

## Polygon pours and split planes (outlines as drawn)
GND on Bottom Layer "Top Layer-No Net 1" (solid, remove dead copper, pour order 27): 0,3145.67 3917.32,3145.67 3917.32,0 0,0
GND on Top Layer "Top Layer-No Net 1" (solid, remove dead copper, pour order 29): 0,0 3917.32,0 3917.32,3145.67 0,3145.67

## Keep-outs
Keep-Out Layer:
  the board outline again, w10

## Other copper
Top Layer:
  rectangle net 3V3: 2212.6,362.2 2401.57,519.68
  rectangle net 3V3: 3381.89,362.2 3570.87,519.68
  rectangle net 3V3: 2803.15,362.2 2984.25,515.75
  rectangle net 3V3: 2440.94,893.7 2586.61,968.5
  rectangle net 3V3: 1110.24,1881.89 1181.1,2208.66
  rectangle net 3V3: 2783.46,1771.65 2940.94,1842.52
  rectangle net 3V3: 2232.28,1775.59 2381.89,1846.46

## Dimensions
0,-23.62 to 3917.32,-23.62 on Top Overlay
